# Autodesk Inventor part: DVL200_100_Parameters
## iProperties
Created: 2009-09
Part Number: DVL200_100_Parameters
Document SubType Name: Modeling
Designer: TB
Density: 1 g/cm^3
Slaglengde: 100.000 mm
Vinkel_Plussport: 0.00 deg
Vinkel_Minusport: 0.00 deg
Forlengelse_rør: 0.000 mm
Author: TB
